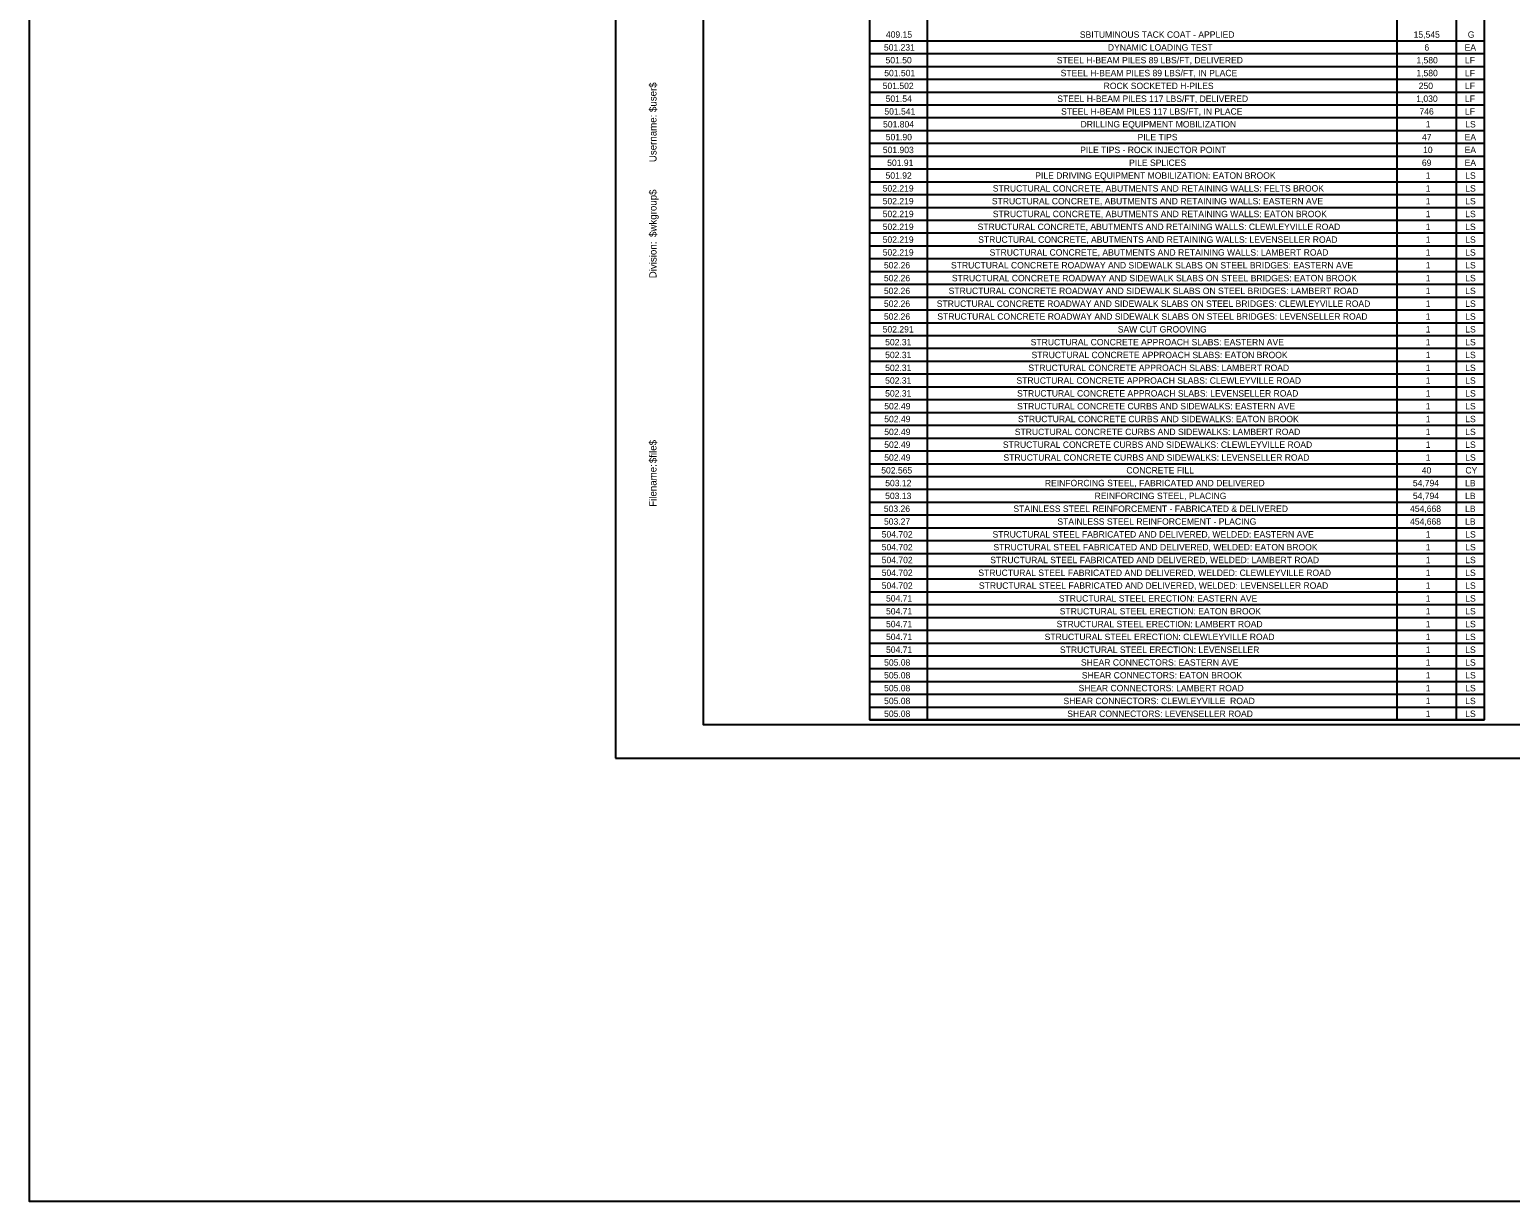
# Model space of a CAD drawing. Extents: x -18.7 to 5.6, y -2.7 to 5.1.
# Drawn here: x -10.815 to -8.539, y 1.503 to 3.303 of the extents above; entities that cross this region are included whole.
import ezdxf

# ---------------------------------------------------------------- set-up
doc = ezdxf.new("R2010")
doc.units = 0
for name, color, linetype in [('ANNOTATION', 7, 'Continuous'), ('BORDER', 7, 'Continuous'), ('Default', 7, 'Continuous'), ('PLOT BOUNDARY', 7, 'Continuous')]:
    doc.layers.add(name, color=color, linetype=linetype)

msp = doc.modelspace()

# ---------------------------------------------------------------- linework, layer by layer
at = {"layer": 'BORDER'}
for p, q in [((-9.4355, 3.9551), (-9.4355, 2.2424)), ((-8.7141, 3.9551), (-8.7141, 2.2424)), ((-8.6227, 3.9551), (-8.6227, 2.2424)), ((-9.524, 3.2858), (-8.5798, 3.2858)), ((-9.524, 3.2661), (-8.5798, 3.2661)), ((-9.524, 3.2464), (-8.5798, 3.2464)), ((-9.524, 3.2267), (-8.5798, 3.2267)), ((-9.524, 3.207), (-8.5798, 3.207)), ((-9.524, 3.1873), (-8.5798, 3.1873)), ((-9.524, 3.1677), (-8.5798, 3.1677)), ((-9.524, 3.148), (-8.5798, 3.148)), ((-9.524, 3.1283), (-8.5798, 3.1283)), ((-9.524, 3.1086), (-8.5798, 3.1086)), ((-9.524, 3.0889), (-8.5798, 3.0889)), ((-9.524, 3.0692), (-8.5798, 3.0692)), ((-9.524, 3.0495), (-8.5798, 3.0495)), ((-9.524, 3.0299), (-8.5798, 3.0299)), ((-9.524, 3.0102), (-8.5798, 3.0102)), ((-9.524, 2.9905), (-8.5798, 2.9905)), ((-9.524, 2.9708), (-8.5798, 2.9708)), ((-9.524, 2.9511), (-8.5798, 2.9511)), ((-9.524, 2.9314), (-8.5798, 2.9314)), ((-9.524, 2.9117), (-8.5798, 2.9117)), ((-9.524, 2.8921), (-8.5798, 2.8921)), ((-9.524, 2.8724), (-8.5798, 2.8724)), ((-9.524, 2.8527), (-8.5798, 2.8527)), ((-9.524, 2.833), (-8.5798, 2.833)), ((-9.524, 2.8133), (-8.5798, 2.8133)), ((-9.524, 2.7936), (-8.5798, 2.7936)), ((-9.524, 2.7739), (-8.5798, 2.7739)), ((-9.524, 2.7543), (-8.5798, 2.7543)), ((-9.524, 2.7346), (-8.5798, 2.7346)), ((-9.524, 2.7149), (-8.5798, 2.7149)), ((-9.524, 2.6952), (-8.5798, 2.6952)), ((-9.524, 2.6755), (-8.5798, 2.6755)), ((-9.524, 2.6558), (-8.5798, 2.6558)), ((-9.524, 2.6361), (-8.5798, 2.6361)), ((-9.524, 2.6165), (-8.5798, 2.6165)), ((-9.524, 2.5968), (-8.5798, 2.5968)), ((-9.524, 2.5771), (-8.5798, 2.5771)), ((-9.524, 2.5574), (-8.5798, 2.5574)), ((-9.524, 2.5377), (-8.5798, 2.5377)), ((-9.524, 2.518), (-8.5798, 2.518)), ((-9.524, 2.4983), (-8.5798, 2.4983)), ((-9.524, 2.4787), (-8.5798, 2.4787)), ((-9.524, 2.459), (-8.5798, 2.459)), ((-9.524, 2.4393), (-8.5798, 2.4393)), ((-9.524, 2.4196), (-8.5798, 2.4196)), ((-9.524, 2.3999), (-8.5798, 2.3999)), ((-9.524, 2.3802), (-8.5798, 2.3802)), ((-9.524, 2.3605), (-8.5798, 2.3605)), ((-9.524, 2.3408), (-8.5798, 2.3408)), ((-9.524, 2.3212), (-8.5798, 2.3212)), ((-9.524, 2.3015), (-8.5798, 2.3015)), ((-9.524, 2.2818), (-8.5798, 2.2818)), ((-9.524, 2.2621), (-8.5798, 2.2621)), ((-9.524, 2.2424), (-8.5798, 2.2424))]:
    msp.add_line(p, q, dxfattribs=at)
for points in [[(-9.7797, 3.9848), (-7.1131, 3.9848), (-7.1131, 2.2348), (-9.7797, 2.2348)], [(-9.524, 3.9748), (-8.5798, 3.9748), (-8.5798, 2.2424), (-9.524, 2.2424)]]:
    msp.add_lwpolyline(points, close=True, dxfattribs=at)
at = {"layer": 'Default'}
msp.add_lwpolyline([(-10.8151, 5.0978), (-2.7516, 5.0978), (-2.7516, 1.5028), (-10.8151, 1.5028)], close=True, dxfattribs=at)
at = {"layer": 'PLOT BOUNDARY'}
msp.add_lwpolyline([(-9.9146, 2.1838), (-7.0813, 2.1838), (-7.0813, 4.0171), (-9.9146, 4.0171)], close=True, dxfattribs=at)

# ---------------------------------------------------------------- texts
at = {"layer": 'ANNOTATION'}
for s, height, p in [('409.15', 0.00984, (-9.4992, 3.2904)), ('SBITUMINOUS TACK COAT - APPLIED', 0.009843, (-9.2011, 3.2904)), ('15,545', 0.00984, (-8.6881, 3.2904)), ('G', 0.00984, (-8.6049, 3.2904)), ('501.231', 0.00984, (-9.5022, 3.2707)), ('DYNAMIC LOADING TEST', 0.009843, (-9.158, 3.2707)), ('6', 0.00984, (-8.6715, 3.2707)), ('EA', 0.00984, (-8.6098, 3.2707)), ('501.50', 0.00984, (-9.4997, 3.251)), ('STEEL H-BEAM PILES 89 LBS/FT, DELIVERED', 0.009843, (-9.2365, 3.251)), ('1,580', 0.00984, (-8.6839, 3.251)), ('LF', 0.00984, (-8.6092, 3.251)), ('501.501', 0.00984, (-9.5017, 3.2313)), ('STEEL H-BEAM PILES 89 LBS/FT, IN PLACE', 0.009843, (-9.2306, 3.2313)), ('1,580', 0.00984, (-8.6839, 3.2313)), ('LF', 0.00984, (-8.6092, 3.2313)), ('501.502', 0.00984, (-9.5041, 3.2116)), ('ROCK SOCKETED H-PILES', 0.009843, (-9.1645, 3.2116)), ('250', 0.00984, (-8.6803, 3.2116)), ('LF', 0.00984, (-8.6092, 3.2116)), ('501.54', 0.00984, (-9.4996, 3.1919)), ('STEEL H-BEAM PILES 117 LBS/FT, DELIVERED', 0.009843, (-9.2358, 3.1919)), ('1,030', 0.00984, (-8.6841, 3.1919)), ('LF', 0.00984, (-8.6092, 3.1919)), ('501.541', 0.00984, (-9.5015, 3.1723)), ('STEEL H-BEAM PILES 117 LBS/FT, IN PLACE', 0.009843, (-9.2299, 3.1723)), ('746', 0.00984, (-8.6792, 3.1723)), ('LF', 0.00984, (-8.6092, 3.1723)), ('501.804', 0.00984, (-9.5035, 3.1526)), ('501.90', 0.00984, (-9.4994, 3.1329)), ('DRILLING EQUIPMENT MOBILIZATION', 0.009843, (-9.2, 3.1526)), ('PILE TIPS', 0.00984, (-9.1124, 3.1329)), ('47', 0.00984, (-8.6752, 3.1329)), ('1', 0.00984, (-8.6695, 3.1526)), ('EA', 0.00984, (-8.6098, 3.1329)), ('LS', 0.00984, (-8.6088, 3.1526)), ('501.903', 0.00984, (-9.5039, 3.1132)), ('PILE TIPS - ROCK INJECTOR POINT', 0.009843, (-9.2006, 3.1132)), ('10', 0.00984, (-8.6736, 3.1132)), ('EA', 0.00984, (-8.6098, 3.1132)), ('501.91', 0.00984, (-9.4972, 3.0935)), ('PILE SPLICES', 0.009843, (-9.1255, 3.0935)), ('69', 0.00984, (-8.6754, 3.0935)), ('EA', 0.00984, (-8.6098, 3.0935)), ('501.92', 0.00984, (-9.4997, 3.0738)), ('PILE DRIVING EQUIPMENT MOBILIZATION: EATON BROOK', 0.009843, (-9.2696, 3.0738)), ('1', 0.00984, (-8.6695, 3.0738)), ('LS', 0.00984, (-8.6088, 3.0738)), ('502.219', 0.00984, (-9.5041, 3.0541)), ('STRUCTURAL CONCRETE, ABUTMENTS AND RETAINING WALLS: FELTS BROOK', 0.009843, (-9.3349, 3.0541)), ('1', 0.00984, (-8.6695, 3.0541)), ('LS', 0.00984, (-8.6088, 3.0541)), ('502.219', 0.00984, (-9.5041, 3.0345)), ('STRUCTURAL CONCRETE, ABUTMENTS AND RETAINING WALLS: EASTERN AVE', 0.009843, (-9.3363, 3.0345)), ('1', 0.00984, (-8.6695, 3.0345)), ('LS', 0.00984, (-8.6088, 3.0345)), ('502.219', 0.00984, (-9.5041, 3.0148)), ('502.219', 0.00984, (-9.5041, 2.9951)), ('STRUCTURAL CONCRETE, ABUTMENTS AND RETAINING WALLS: CLEWLEYVILLE ROAD', 0.009843, (-9.3582, 2.9951)), ('STRUCTURAL CONCRETE, ABUTMENTS AND RETAINING WALLS: EATON BROOK', 0.009843, (-9.3349, 3.0148)), ('1', 0.00984, (-8.6695, 3.0148)), ('1', 0.00984, (-8.6695, 2.9951)), ('LS', 0.00984, (-8.6088, 3.0148)), ('LS', 0.00984, (-8.6088, 2.9951)), ('502.219', 0.00984, (-9.5041, 2.9754)), ('STRUCTURAL CONCRETE, ABUTMENTS AND RETAINING WALLS: LEVENSELLER ROAD', 0.009843, (-9.3573, 2.9754)), ('1', 0.00984, (-8.6695, 2.9754)), ('LS', 0.00984, (-8.6088, 2.9754)), ('502.219', 0.00984, (-9.5041, 2.9557)), ('STRUCTURAL CONCRETE, ABUTMENTS AND RETAINING WALLS: LAMBERT ROAD', 0.009843, (-9.3398, 2.9557)), ('1', 0.00984, (-8.6695, 2.9557)), ('LS', 0.00984, (-8.6088, 2.9557)), ('502.26', 0.00984, (-9.5022, 2.936)), ('STRUCTURAL CONCRETE ROADWAY AND SIDEWALK SLABS ON STEEL BRIDGES: EASTERN AVE', 0.009843, (-9.3991, 2.936)), ('1', 0.00984, (-8.6695, 2.936)), ('LS', 0.00984, (-8.6088, 2.936)), ('502.26', 0.00984, (-9.5022, 2.9163)), ('STRUCTURAL CONCRETE ROADWAY AND SIDEWALK SLABS ON STEEL BRIDGES: EATON BROOK', 0.009843, (-9.3978, 2.9163)), ('1', 0.00984, (-8.6695, 2.9163)), ('LS', 0.00984, (-8.6088, 2.9163)), ('502.26', 0.00984, (-9.5022, 2.8967)), ('STRUCTURAL CONCRETE ROADWAY AND SIDEWALK SLABS ON STEEL BRIDGES: LAMBERT ROAD', 0.009843, (-9.4027, 2.8967)), ('1', 0.00984, (-8.6695, 2.8967)), ('LS', 0.00984, (-8.6088, 2.8967)), ('502.26', 0.00984, (-9.5022, 2.877)), ('STRUCTURAL CONCRETE ROADWAY AND SIDEWALK SLABS ON STEEL BRIDGES: CLEWLEYVILLE ROAD', 0.009843, (-9.421, 2.877)), ('1', 0.00984, (-8.6695, 2.877)), ('LS', 0.00984, (-8.6088, 2.877)), ('502.291', 0.00984, (-9.5041, 2.8376)), ('502.26', 0.00984, (-9.5022, 2.8573)), ('STRUCTURAL CONCRETE ROADWAY AND SIDEWALK SLABS ON STEEL BRIDGES: LEVENSELLER ROAD', 0.009843, (-9.4201, 2.8573)), ('SAW CUT GROOVING', 0.009843, (-9.1428, 2.8376)), ('1', 0.00984, (-8.6695, 2.8573)), ('1', 0.00984, (-8.6695, 2.8376)), ('LS', 0.00984, (-8.6088, 2.8573)), ('LS', 0.00984, (-8.6088, 2.8376)), ('502.31', 0.00984, (-9.5003, 2.8179)), ('STRUCTURAL CONCRETE APPROACH SLABS: EASTERN AVE', 0.009843, (-9.2766, 2.8179)), ('1', 0.00984, (-8.6695, 2.8179)), ('LS', 0.00984, (-8.6088, 2.8179)), ('502.31', 0.00984, (-9.5003, 2.7982)), ('STRUCTURAL CONCRETE APPROACH SLABS: EATON BROOK', 0.009843, (-9.2753, 2.7982)), ('1', 0.00984, (-8.6695, 2.7982)), ('LS', 0.00984, (-8.6088, 2.7982)), ('502.31', 0.00984, (-9.5003, 2.7785)), ('STRUCTURAL CONCRETE APPROACH SLABS: LAMBERT ROAD', 0.009843, (-9.2802, 2.7785)), ('1', 0.00984, (-8.6695, 2.7785)), ('LS', 0.00984, (-8.6088, 2.7785)), ('502.31', 0.00984, (-9.5003, 2.7589)), ('STRUCTURAL CONCRETE APPROACH SLABS: CLEWLEYVILLE ROAD', 0.009843, (-9.2985, 2.7589)), ('1', 0.00984, (-8.6695, 2.7589)), ('LS', 0.00984, (-8.6088, 2.7589)), ('502.31', 0.00984, (-9.5003, 2.7392)), ('STRUCTURAL CONCRETE APPROACH SLABS: LEVENSELLER ROAD', 0.009843, (-9.2976, 2.7392)), ('1', 0.00984, (-8.6695, 2.7392)), ('LS', 0.00984, (-8.6088, 2.7392)), ('502.49', 0.00984, (-9.5017, 2.7195)), ('502.49', 0.00984, (-9.5017, 2.6998)), ('STRUCTURAL CONCRETE CURBS AND SIDEWALKS: EASTERN AVE', 0.009843, (-9.2975, 2.7195)), ('STRUCTURAL CONCRETE CURBS AND SIDEWALKS: EATON BROOK', 0.009843, (-9.2962, 2.6998)), ('1', 0.00984, (-8.6695, 2.7195)), ('1', 0.00984, (-8.6695, 2.6998)), ('LS', 0.00984, (-8.6088, 2.7195)), ('LS', 0.00984, (-8.6088, 2.6998)), ('502.49', 0.00984, (-9.5017, 2.6801)), ('STRUCTURAL CONCRETE CURBS AND SIDEWALKS: LAMBERT ROAD', 0.009843, (-9.3011, 2.6801)), ('1', 0.00984, (-8.6695, 2.6801)), ('LS', 0.00984, (-8.6088, 2.6801)), ('502.49', 0.00984, (-9.5017, 2.6604)), ('STRUCTURAL CONCRETE CURBS AND SIDEWALKS: CLEWLEYVILLE ROAD', 0.009843, (-9.3194, 2.6604)), ('1', 0.00984, (-8.6695, 2.6604)), ('LS', 0.00984, (-8.6088, 2.6604)), ('502.49', 0.00984, (-9.5017, 2.6407)), ('STRUCTURAL CONCRETE CURBS AND SIDEWALKS: LEVENSELLER ROAD', 0.009843, (-9.3185, 2.6407)), ('1', 0.00984, (-8.6695, 2.6407)), ('LS', 0.00984, (-8.6088, 2.6407)), ('502.565', 0.00984, (-9.5063, 2.621)), ('CONCRETE FILL', 0.009843, (-9.1296, 2.621)), ('40', 0.00984, (-8.6756, 2.621)), ('CY', 0.00984, (-8.6086, 2.621)), ('503.12', 0.00984, (-9.5002, 2.6014)), ('REINFORCING STEEL, FABRICATED AND DELIVERED', 0.009843, (-9.2549, 2.6014)), ('54,794', 0.00984, (-8.6893, 2.6014)), ('LB', 0.00984, (-8.609, 2.6014)), ('503.26', 0.00984, (-9.5023, 2.562)), ('503.13', 0.00984, (-9.5003, 2.5817)), ('STAINLESS STEEL REINFORCEMENT - FABRICATED & DELIVERED', 0.009843, (-9.3032, 2.562)), ('REINFORCING STEEL, PLACING', 0.009843, (-9.1784, 2.5817)), ('454,668', 0.00984, (-8.6936, 2.562)), ('54,794', 0.00984, (-8.6893, 2.5817)), ('LB', 0.00984, (-8.609, 2.5817)), ('LB', 0.00984, (-8.609, 2.562)), ('503.27', 0.00984, (-9.5021, 2.5423)), ('STAINLESS STEEL REINFORCEMENT - PLACING', 0.009843, (-9.2356, 2.5423)), ('454,668', 0.00984, (-8.6936, 2.5423)), ('LB', 0.00984, (-8.609, 2.5423)), ('504.702', 0.00984, (-9.5056, 2.5226)), ('STRUCTURAL STEEL FABRICATED AND DELIVERED, WELDED: EASTERN AVE', 0.009843, (-9.3353, 2.5226)), ('1', 0.00984, (-8.6695, 2.5226)), ('LS', 0.00984, (-8.6088, 2.5226)), ('504.702', 0.00984, (-9.5056, 2.5029)), ('STRUCTURAL STEEL FABRICATED AND DELIVERED, WELDED: EATON BROOK', 0.009843, (-9.3339, 2.5029)), ('1', 0.00984, (-8.6695, 2.5029)), ('LS', 0.00984, (-8.6088, 2.5029)), ('504.702', 0.00984, (-9.5056, 2.4832)), ('STRUCTURAL STEEL FABRICATED AND DELIVERED, WELDED: LAMBERT ROAD', 0.009843, (-9.3388, 2.4832)), ('1', 0.00984, (-8.6695, 2.4832)), ('LS', 0.00984, (-8.6088, 2.4832)), ('504.702', 0.00984, (-9.5056, 2.4636)), ('STRUCTURAL STEEL FABRICATED AND DELIVERED, WELDED: CLEWLEYVILLE ROAD', 0.009843, (-9.3571, 2.4636)), ('1', 0.00984, (-8.6695, 2.4636)), ('LS', 0.00984, (-8.6088, 2.4636)), ('504.702', 0.00984, (-9.5056, 2.4439)), ('STRUCTURAL STEEL FABRICATED AND DELIVERED, WELDED: LEVENSELLER ROAD', 0.009843, (-9.3562, 2.4439)), ('1', 0.00984, (-8.6695, 2.4439)), ('LS', 0.00984, (-8.6088, 2.4439)), ('504.71', 0.00984, (-9.499, 2.4242)), ('504.71', 0.00984, (-9.499, 2.4045)), ('STRUCTURAL STEEL ERECTION: EASTERN AVE', 0.009843, (-9.2334, 2.4242)), ('STRUCTURAL STEEL ERECTION: EATON BROOK', 0.009843, (-9.232, 2.4045)), ('1', 0.00984, (-8.6695, 2.4242)), ('1', 0.00984, (-8.6695, 2.4045)), ('LS', 0.00984, (-8.6088, 2.4242)), ('LS', 0.00984, (-8.6088, 2.4045)), ('504.71', 0.00984, (-9.499, 2.3848)), ('STRUCTURAL STEEL ERECTION: LAMBERT ROAD', 0.009843, (-9.2369, 2.3848)), ('1', 0.00984, (-8.6695, 2.3848)), ('LS', 0.00984, (-8.6088, 2.3848)), ('504.71', 0.00984, (-9.499, 2.3651)), ('STRUCTURAL STEEL ERECTION: CLEWLEYVILLE ROAD', 0.009843, (-9.2552, 2.3651)), ('1', 0.00984, (-8.6695, 2.3651)), ('LS', 0.00984, (-8.6088, 2.3651)), ('504.71', 0.00984, (-9.499, 2.3454)), ('STRUCTURAL STEEL ERECTION: LEVENSELLER', 0.009843, (-9.2317, 2.3454)), ('1', 0.00984, (-8.6695, 2.3454)), ('LS', 0.00984, (-8.6088, 2.3454)), ('505.08', 0.00984, (-9.5019, 2.3258)), ('SHEAR CONNECTORS: EASTERN AVE', 0.009843, (-9.1994, 2.3258)), ('1', 0.00984, (-8.6695, 2.3258)), ('LS', 0.00984, (-8.6088, 2.3258)), ('505.08', 0.00984, (-9.5019, 2.3061)), ('SHEAR CONNECTORS: EATON BROOK', 0.009843, (-9.1981, 2.3061)), ('1', 0.00984, (-8.6695, 2.3061)), ('LS', 0.00984, (-8.6088, 2.3061)), ('505.08', 0.00984, (-9.5019, 2.2864)), ('505.08', 0.00984, (-9.5019, 2.2667)), ('SHEAR CONNECTORS: CLEWLEYVILLE  ROAD', 0.009843, (-9.2262, 2.2667)), ('SHEAR CONNECTORS: LAMBERT ROAD', 0.009843, (-9.203, 2.2864)), ('1', 0.00984, (-8.6695, 2.2864)), ('1', 0.00984, (-8.6695, 2.2667)), ('LS', 0.00984, (-8.6088, 2.2864)), ('LS', 0.00984, (-8.6088, 2.2667)), ('505.08', 0.00984, (-9.5019, 2.247)), ('SHEAR CONNECTORS: LEVENSELLER ROAD', 0.009843, (-9.2204, 2.247)), ('1', 0.00984, (-8.6695, 2.247)), ('LS', 0.00984, (-8.6088, 2.247))]:
    msp.add_text(s, height=height, dxfattribs=at).set_placement(p)
at = {"layer": 'BORDER'}
for s, p in [('$user$', (-9.8517, 3.1763)), ('Username:', (-9.8517, 3.0993)), ('$wkgroup$', (-9.8517, 2.9843)), ('Division:', (-9.8517, 2.9209)), ('$file$', (-9.8517, 2.6369)), ('Filename:', (-9.8517, 2.5698))]:
    msp.add_text(s, height=0.01116, rotation=90, dxfattribs=at).set_placement(p)

doc.saveas('drawing.dxf')
